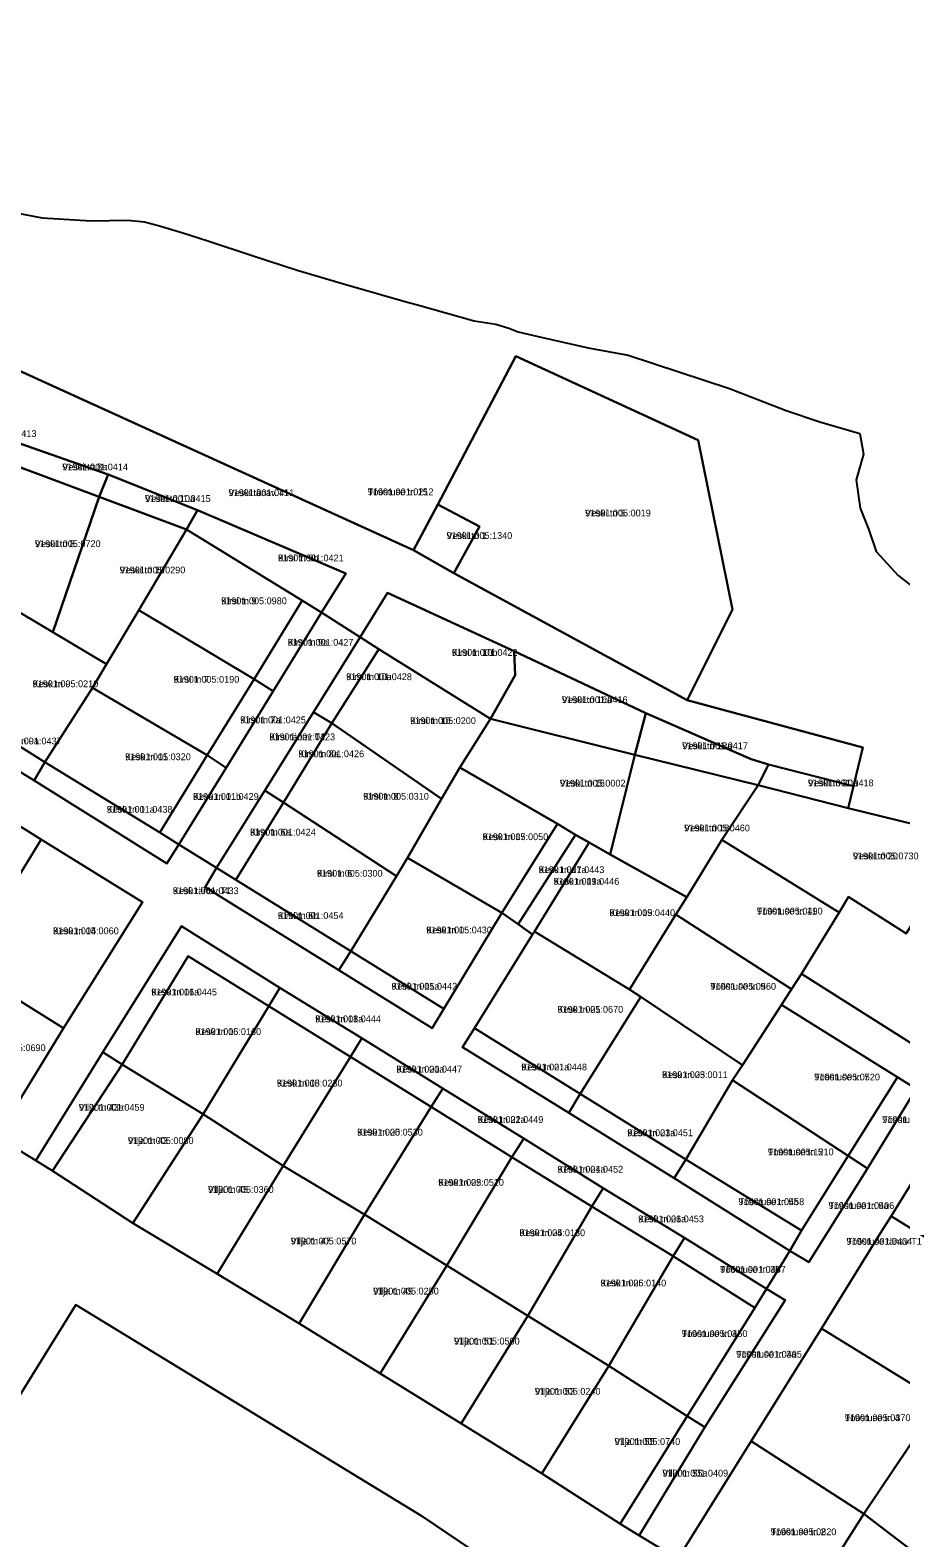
# Model space of a CAD drawing. Extents: x 675810 to 681273, y 6411190 to 6417565.
# Drawn here: x 679020.6 to 679212.9, y 6415637.7 to 6415970.5 of the extents above; entities that cross this region are included whole.
import ezdxf

# ---------------------------------------------------------------- set-up
doc = ezdxf.new("R2010")
doc.units = 0
for name, color, linetype in [('L_AADRESS', 7, 'Continuous'), ('PIIR', 7, 'Continuous'), ('TUNNUS', 7, 'Continuous')]:
    doc.layers.add(name, color=color, linetype=linetype)

msp = doc.modelspace()

# ---------------------------------------------------------------- linework, layer by layer
at = {"layer": 'PIIR'}
for points in [[(679418.32, 6415681.66), (679372.45, 6415703.1), (679376.15, 6415709.11), (679339.93, 6415731.36), (679341.68, 6415734.46), (679247.81, 6415787.97), (679240.52, 6415784.31), (679227.34, 6415792.31), (679201.2, 6415798.72), (679202.38, 6415803.59), (679204.44, 6415812.13), (679165.65, 6415822.55), (679175.65, 6415842.58), (679168.11, 6415879.95), (679127.82, 6415898.47), (679110.64, 6415865.76), (679105.26, 6415855.66), (678938.35, 6415931.63), (678872.23, 6415963.49), (678840.09, 6415967.49), (678816.91, 6415970.45)], [(679012.5, 6415931.11), (679023.26, 6415929.06), (679034.04, 6415928.4), (679042.16, 6415928.54), (679045.83, 6415928.14), (679049.13, 6415927.27), (679054.3, 6415925.72), (679059.82, 6415923.96), (679069.61, 6415920.74), (679079.59, 6415917.48), (679090.33, 6415914.31), (679103.61, 6415910.5), (679106.1, 6415909.8), (679118.61, 6415906.26), (679123.43, 6415905.59), (679126.31, 6415904.7), (679128.36, 6415903.87), (679132.78, 6415902.83), (679143.79, 6415900.33), (679152.61, 6415898.74), (679175.03, 6415891.38), (679187.53, 6415886.48), (679194.97, 6415884), (679203.78, 6415881.45), (679204.58, 6415876.83), (679202.98, 6415871.19), (679203.84, 6415864.94), (679205.8, 6415860.17), (679207.43, 6415855.35), (679212.29, 6415850.08), (679215.84, 6415847.26)], [(678819.79, 6415844.47), (678838.07, 6415834.5), (678867.97, 6415815.62), (678879.6, 6415808.84), (678883.9, 6415806.35), (678901.67, 6415794.69), (678919.6, 6415783.76), (678937.53, 6415772.83), (678955.46, 6415761.9), (678973.27, 6415750.97), (678991.08, 6415739.95), (679013.28, 6415726.22), (679021.83, 6415720.99), (679025.55, 6415718.7), (679043.31, 6415707.12), (679061.88, 6415695.92), (679080, 6415684.98), (679097.88, 6415673.97), (679115.74, 6415662.92), (679133.58, 6415651.86), (679150.85, 6415640.79), (679155.1, 6415638.2), (679163.58, 6415633.02)], [(679002.22, 6415816.67), (679021.5, 6415804.84), (679050.78, 6415786.53), (679053.4, 6415790.68), (679061.78, 6415785.53), (679059.22, 6415781.3), (679088.73, 6415763), (679109.36, 6415750.16), (679111.92, 6415754.42), (679124.73, 6415775.65), (679128.33, 6415773.12), (679131.49, 6415770.86), (679118.72, 6415750.19), (679116.09, 6415745.97), (679139.51, 6415731.51), (679162.79, 6415717.04), (679188.31, 6415701.04), (679183.17, 6415692.68), (679165.05, 6415703.91), (679147.11, 6415714.83), (679129.63, 6415725.8), (679111.7, 6415736.84), (679093.84, 6415747.95), (679075.75, 6415759.1), (679053.99, 6415772.66), (679036.68, 6415744.85), (679021.83, 6415720.99), (679013.28, 6415726.22), (679027.96, 6415750.19), (679045.44, 6415777.97), (679023.06, 6415791.8), (679005.36, 6415802.84)], [(679209.06, 6415573.64), (679107.25, 6415642.36), (679030.7, 6415689.1), (678989.81, 6415623.26)]]:
    msp.add_lwpolyline(points, dxfattribs=at)
for points in [[(678929.48, 6415916.98), (678938.35, 6415931.63), (679105.26, 6415855.66), (679114.18, 6415850.62), (679165.65, 6415822.55), (679204.44, 6415812.13), (679202.38, 6415803.59), (679183.64, 6415808.38), (679179.78, 6415809.54), (679156.58, 6415819.69), (679127.49, 6415833.35), (679099.54, 6415846.24), (679093.45, 6415836.45), (679084.93, 6415841.89), (679090.32, 6415850.54), (679057.56, 6415864.54), (679037.79, 6415872.39), (679018.58, 6415879.14), (678998.13, 6415886.78), (678998.97, 6415889.41), (678974.02, 6415900.22), (678944.77, 6415913.36), (678942.12, 6415909.13)], [(679127.82, 6415898.47), (679168.11, 6415879.95), (679175.65, 6415842.58), (679165.65, 6415822.55), (679114.18, 6415850.62), (679119.84, 6415860.93), (679110.64, 6415865.76)], [(679016.9, 6415874.51), (679018.58, 6415879.14), (679037.79, 6415872.39), (679035.82, 6415867.44)], [(679025.58, 6415837.61), (679018.34, 6415841.95), (679007.49, 6415848.26), (679016.9, 6415874.51), (679035.82, 6415867.44)], [(679035.82, 6415867.44), (679037.79, 6415872.39), (679057.56, 6415864.54), (679055.14, 6415860.24)], [(679025.58, 6415837.61), (679035.82, 6415867.44), (679055.14, 6415860.24), (679044.59, 6415842.43), (679037.46, 6415830.49)], [(679119.84, 6415860.93), (679114.18, 6415850.62), (679105.26, 6415855.66), (679110.64, 6415865.76)], [(679055.14, 6415860.24), (679057.56, 6415864.54), (679090.32, 6415850.54), (679084.93, 6415841.89), (679080.68, 6415844.57)], [(679070.04, 6415827.24), (679044.59, 6415842.43), (679055.14, 6415860.24), (679080.68, 6415844.57)], [(679097.6, 6415833.8), (679093.45, 6415836.45), (679099.54, 6415846.24), (679127.49, 6415833.35), (679127.73, 6415828.09), (679122.23, 6415818.46)], [(679059.7, 6415810.41), (679034.34, 6415825.26), (679037.46, 6415830.49), (679044.59, 6415842.43), (679070.04, 6415827.24)], [(679074.26, 6415824.58), (679070.04, 6415827.24), (679080.68, 6415844.57), (679084.93, 6415841.89)], [(679025.58, 6415837.61), (679037.46, 6415830.49), (679034.34, 6415825.26), (679023.84, 6415808.91), (679004.82, 6415820.78), (679018.34, 6415841.95)], [(679061.78, 6415785.53), (679053.4, 6415790.68), (679063.89, 6415807.64), (679074.26, 6415824.58), (679084.93, 6415841.89), (679093.45, 6415836.45), (679083.18, 6415819.94), (679072.44, 6415802.64)], [(679087.24, 6415817.5), (679083.18, 6415819.94), (679093.45, 6415836.45), (679097.6, 6415833.8)], [(679097.6, 6415833.8), (679122.23, 6415818.46), (679115.45, 6415807.71), (679111.45, 6415800.77), (679087.24, 6415817.5)], [(679127.73, 6415828.09), (679127.49, 6415833.35), (679156.58, 6415819.69), (679154.08, 6415810.49), (679122.23, 6415818.46)], [(679063.89, 6415807.64), (679059.7, 6415810.41), (679070.04, 6415827.24), (679074.26, 6415824.58)], [(679034.34, 6415825.26), (679059.7, 6415810.41), (679049.25, 6415793.38), (679023.84, 6415808.91)], [(679002.22, 6415816.67), (679004.82, 6415820.78), (679023.84, 6415808.91), (679021.5, 6415804.84)], [(679076.54, 6415800.01), (679072.44, 6415802.64), (679083.18, 6415819.94), (679087.24, 6415817.5)], [(679154.08, 6415810.49), (679156.58, 6415819.69), (679179.78, 6415809.54), (679183.64, 6415808.38), (679181.33, 6415803.8)], [(679087.24, 6415817.5), (679111.45, 6415800.77), (679103.93, 6415787.8), (679101.47, 6415783.7), (679076.54, 6415800.01)], [(679137.06, 6415795.24), (679115.45, 6415807.71), (679122.23, 6415818.46), (679154.08, 6415810.49), (679148.7, 6415788.53), (679144.04, 6415791.13), (679141.04, 6415792.83)], [(679053.4, 6415790.68), (679049.25, 6415793.38), (679059.7, 6415810.41), (679063.89, 6415807.64)], [(679173.32, 6415791.71), (679165.58, 6415779.09), (679148.7, 6415788.53), (679154.08, 6415810.49), (679181.33, 6415803.8)], [(679021.5, 6415804.84), (679023.84, 6415808.91), (679049.25, 6415793.38), (679053.4, 6415790.68), (679050.78, 6415786.53)], [(679124.73, 6415775.65), (679103.93, 6415787.8), (679111.45, 6415800.77), (679115.45, 6415807.71), (679137.06, 6415795.24)], [(679181.33, 6415803.8), (679183.64, 6415808.38), (679202.38, 6415803.59), (679201.2, 6415798.72)], [(678988.02, 6415774.82), (679002.54, 6415798.78), (679005.36, 6415802.84), (679023.06, 6415791.8), (679005.89, 6415763.94)], [(679066.04, 6415782.94), (679061.78, 6415785.53), (679072.44, 6415802.64), (679076.54, 6415800.01)], [(679227.34, 6415792.31), (679214.01, 6415771.08), (679201.32, 6415779.15), (679199.24, 6415775.74), (679173.32, 6415791.71), (679181.33, 6415803.8), (679201.2, 6415798.72)], [(679076.54, 6415800.01), (679101.47, 6415783.7), (679091.4, 6415767.19), (679066.04, 6415782.94)], [(679128.33, 6415773.12), (679124.73, 6415775.65), (679137.06, 6415795.24), (679141.04, 6415792.83)], [(679128.33, 6415773.12), (679141.04, 6415792.83), (679144.04, 6415791.13), (679131.96, 6415771.5), (679131.49, 6415770.86)], [(679023.06, 6415791.8), (679045.44, 6415777.97), (679027.96, 6415750.19), (679005.89, 6415763.94)], [(679163.17, 6415775.29), (679152.92, 6415758.7), (679131.96, 6415771.5), (679144.04, 6415791.13), (679148.7, 6415788.53), (679165.58, 6415779.09)], [(679163.17, 6415775.29), (679165.58, 6415779.09), (679173.32, 6415791.71), (679199.24, 6415775.74), (679190.94, 6415762.16), (679188.68, 6415758.8)], [(679240.52, 6415784.31), (679234.07, 6415774.13), (679216.42, 6415746.08), (679190.94, 6415762.16), (679199.24, 6415775.74), (679201.32, 6415779.15), (679214.01, 6415771.08), (679227.34, 6415792.31)], [(679101.47, 6415783.7), (679103.93, 6415787.8), (679124.73, 6415775.65), (679111.92, 6415754.42), (679091.4, 6415767.19)], [(679059.22, 6415781.3), (679061.78, 6415785.53), (679066.04, 6415782.94), (679091.4, 6415767.19), (679088.73, 6415763)], [(679040.9, 6415742.15), (679036.68, 6415744.85), (679053.99, 6415772.66), (679075.75, 6415759.1), (679073.28, 6415755.01), (679055.47, 6415766.07)], [(679155.46, 6415757.09), (679152.92, 6415758.7), (679163.17, 6415775.29), (679188.68, 6415758.8), (679186.52, 6415755.32), (679177.89, 6415742.04)], [(679131.96, 6415771.5), (679152.92, 6415758.7), (679155.46, 6415757.09), (679142.08, 6415735.65), (679118.72, 6415750.19), (679131.49, 6415770.86)], [(679163.58, 6415633.02), (679155.1, 6415638.2), (679169.58, 6415662.1), (679187.29, 6415690.12), (679183.17, 6415692.68), (679188.31, 6415701.04), (679192.5, 6415698.51), (679205.47, 6415719.21), (679216.26, 6415736.76), (679212.15, 6415739.39), (679186.52, 6415755.32), (679188.68, 6415758.8), (679190.94, 6415762.16), (679216.42, 6415746.08), (679220.47, 6415743.64), (679237.97, 6415771.73), (679246.64, 6415766.45), (679226.57, 6415734.31), (679210.69, 6415708.71), (679208.62, 6415705.42), (679195.3, 6415683.87), (679179.77, 6415659.03)], [(679040.9, 6415742.15), (679055.47, 6415766.07), (679073.28, 6415755.01), (679058.83, 6415731.21)], [(679088.73, 6415763), (679091.4, 6415767.19), (679111.92, 6415754.42), (679109.36, 6415750.16)], [(679005.89, 6415763.94), (679027.96, 6415750.19), (679013.28, 6415726.22), (678991.08, 6415739.95)], [(679073.28, 6415755.01), (679075.75, 6415759.1), (679093.84, 6415747.95), (679091.31, 6415743.86)], [(679142.08, 6415735.65), (679155.46, 6415757.09), (679177.89, 6415742.04), (679175.71, 6415738.7), (679165.37, 6415721.21)], [(679058.83, 6415731.21), (679073.28, 6415755.01), (679091.31, 6415743.86), (679076.44, 6415719.81)], [(679175.71, 6415738.7), (679177.89, 6415742.04), (679186.52, 6415755.32), (679212.15, 6415739.39), (679201.22, 6415721.97)], [(679116.09, 6415745.97), (679118.72, 6415750.19), (679142.08, 6415735.65), (679139.51, 6415731.51)], [(679091.31, 6415743.86), (679093.84, 6415747.95), (679111.7, 6415736.84), (679109.13, 6415732.8)], [(679025.55, 6415718.7), (679021.83, 6415720.99), (679036.68, 6415744.85), (679040.9, 6415742.15)], [(679094.42, 6415709.02), (679076.44, 6415719.81), (679091.31, 6415743.86), (679109.13, 6415732.8)], [(679043.31, 6415707.12), (679025.55, 6415718.7), (679040.9, 6415742.15), (679058.83, 6415731.21)], [(679205.47, 6415719.21), (679201.22, 6415721.97), (679212.15, 6415739.39), (679216.26, 6415736.76)], [(679109.13, 6415732.8), (679111.7, 6415736.84), (679129.63, 6415725.8), (679126.99, 6415721.69)], [(679190.95, 6415705.51), (679165.37, 6415721.21), (679175.71, 6415738.7), (679201.24, 6415722.02)], [(679112.63, 6415697.78), (679094.42, 6415709.02), (679109.13, 6415732.8), (679126.99, 6415721.69)], [(679139.51, 6415731.51), (679142.08, 6415735.65), (679165.37, 6415721.21), (679162.79, 6415717.04)], [(679210.69, 6415708.71), (679226.57, 6415734.31), (679253.82, 6415718.26), (679248.54, 6415710.1), (679237.06, 6415692.46)], [(679043.31, 6415707.12), (679058.83, 6415731.21), (679076.44, 6415719.81), (679061.88, 6415695.92)], [(679126.99, 6415721.69), (679129.63, 6415725.8), (679147.11, 6415714.83), (679144.63, 6415710.79)], [(679076.44, 6415719.81), (679094.42, 6415709.02), (679080, 6415684.98), (679061.88, 6415695.92)], [(679112.63, 6415697.78), (679126.99, 6415721.69), (679144.63, 6415710.79), (679130.5, 6415686.71)], [(679162.79, 6415717.04), (679165.37, 6415721.21), (679190.95, 6415705.51), (679188.31, 6415701.04)], [(679192.5, 6415698.51), (679188.31, 6415701.04), (679190.95, 6415705.51), (679201.22, 6415721.97), (679205.47, 6415719.21)], [(679144.63, 6415710.79), (679147.11, 6415714.83), (679165.05, 6415703.91), (679162.61, 6415699.84)], [(679130.5, 6415686.71), (679144.63, 6415710.79), (679162.61, 6415699.84), (679148.34, 6415675.64)], [(679237.06, 6415692.46), (679248.54, 6415710.1), (679277.39, 6415691.1), (679306.26, 6415672.05), (679335.12, 6415653.05), (679316.48, 6415618.21), (679301.31, 6415612.53), (679223.54, 6415583.42), (679222.37, 6415587.28), (679259.47, 6415601.16), (679204.65, 6415643.01), (679221.39, 6415667.86)], [(679080, 6415684.98), (679094.42, 6415709.02), (679112.63, 6415697.78), (679097.88, 6415673.97)], [(679237.06, 6415692.46), (679221.39, 6415667.86), (679195.3, 6415683.87), (679208.62, 6415705.42), (679210.69, 6415708.71)], [(679162.61, 6415699.84), (679165.05, 6415703.91), (679183.17, 6415692.68), (679180.61, 6415688.47)], [(679180.61, 6415688.47), (679165.7, 6415664.57), (679148.34, 6415675.64), (679162.61, 6415699.84)], [(679097.88, 6415673.97), (679112.63, 6415697.78), (679130.5, 6415686.71), (679115.74, 6415662.92)], [(679169.58, 6415662.1), (679165.7, 6415664.57), (679180.61, 6415688.47), (679183.17, 6415692.68), (679187.29, 6415690.12)], [(679107.25, 6415642.36), (679209.06, 6415573.64), (679235.94, 6415523.12), (679269.34, 6415417.57), (679263.6, 6415410.66), (679213.57, 6415387.53), (679202.07, 6415417.43), (679144.86, 6415396.49), (679135.51, 6415422.06), (679089.93, 6415556), (679070.56, 6415610.67), (679030.28, 6415597.11), (678989.81, 6415623.26), (679030.7, 6415689.1)], [(679115.74, 6415662.92), (679130.5, 6415686.71), (679148.34, 6415675.64), (679133.58, 6415651.86)], [(679195.3, 6415683.87), (679221.39, 6415667.86), (679204.65, 6415643.01), (679179.77, 6415659.03)], [(679133.58, 6415651.86), (679148.34, 6415675.64), (679165.7, 6415664.57), (679150.85, 6415640.79)], [(679155.1, 6415638.2), (679150.85, 6415640.79), (679165.7, 6415664.57), (679169.58, 6415662.1)], [(679204.65, 6415643.01), (679188.58, 6415617.54), (679163.58, 6415633.02), (679179.77, 6415659.03)], [(679188.58, 6415617.54), (679204.65, 6415643.01), (679259.47, 6415601.16), (679222.37, 6415587.28), (679221.77, 6415588.98), (679208.41, 6415599.7), (679186.54, 6415614.19)]]:
    msp.add_lwpolyline(points, close=True, dxfattribs=at)

# ---------------------------------------------------------------- texts
at = {"layer": 'L_AADRESS'}
for s, p in [('Veski tn 8a', (679027.7, 6415873.29)), ('Veski tänav T1', (679064.42, 6415867.61)), ('Tööstuse tn 15', (679095.15, 6415867.8)), ('Veski tn 10a', (679045.96, 6415866.32)), ('Veski tn 3', (679143.14, 6415863.12)), ('Veski tn 1', (679112.55, 6415858.15)), ('Veski tn 8', (679021.66, 6415856.35)), ('Kirsi tn 9b', (679075.33, 6415853.21)), ('Veski tn 10', (679040.36, 6415850.55)), ('Kirsi tn 9', (679062.77, 6415843.74)), ('Kirsi tn 9a', (679077.48, 6415834.59)), ('Kirsi tn 10b', (679113.73, 6415832.35)), ('Kesk tn 9', (679021.14, 6415825.43)), ('Kirsi tn 7', (679052.28, 6415826.42)), ('Kirsi tn 10a', (679090.39, 6415826.99)), ('Veski tn 16a', (679138.02, 6415821.92)), ('Kirsi tn 7a', (679066.98, 6415817.47)), ('Kirsi tn 10', (679104.52, 6415817.29)), ('Kesk tn 9a', (679013.05, 6415812.81)), ('Kirsi tänav T1', (679073.43, 6415813.72)), ('Veski tn 18a', (679164.58, 6415811.75)), ('Kesk tn 11', (679041.57, 6415809.32)), ('Kirsi tn 8a', (679079.84, 6415809.98)), ('Veski tn 16', (679137.56, 6415803.5)), ('Veski tn 20a', (679192.34, 6415803.55)), ('Kesk tn 11a', (679037.52, 6415797.72)), ('Kesk tn 11b', (679056.57, 6415800.56)), ('Kirsi tn 8', (679094.13, 6415800.6)), ('Kirsi tn 6a', (679069.16, 6415792.69)), ('Kesk tn 17', (679120.5, 6415791.68)), ('Veski tn 18', (679165.02, 6415793.61)), ('Kesk tn 17a', (679132.88, 6415784.4)), ('Veski tn 20', (679202.27, 6415787.44)), ('Kirsi tn 6', (679083.93, 6415783.6)), ('Kesk tn 19a', (679136.18, 6415781.83)), ('Kesk tänav T1', (679052.12, 6415779.76)), ('Kirsi tn 6b', (679075.29, 6415774.27)), ('Kesk tn 19', (679148.5, 6415774.91)), ('Tööstuse tn 11', (679181.08, 6415775.26)), ('Kesk tn 14', (679025.66, 6415770.91)), ('Kesk tn 15', (679108.06, 6415771.1)), ('Kesk tn 15a', (679100.38, 6415758.68)), ('Tööstuse tn 9', (679170.79, 6415758.66)), ('Kesk tn 16a', (679047.34, 6415757.4)), ('Kesk tn 18a', (679083.55, 6415751.48)), ('Kesk tn 21', (679137.04, 6415753.57)), ('Kesk tn 16', (679057.09, 6415748.67)), ('Kesk tn 20a', (679101.47, 6415740.38)), ('Kesk tn 21a', (679129.05, 6415740.85)), ('Kesk tn 23', (679160.13, 6415739.15)), ('Tööstuse tn 7', (679193.74, 6415738.65)), ('Kesk tn 18', (679075.07, 6415737.3)), ('Vilja tn 43a', (679031.36, 6415731.95)), ('Kesk tn 22a', (679119.41, 6415729.27)), ('Tööstuse tn 7a', (679208.74, 6415729.24)), ('Vilja tn 43', (679042.19, 6415724.61)), ('Kesk tn 20', (679092.79, 6415726.47)), ('Kesk tn 23a', (679152.45, 6415726.34)), ('Tööstuse tn 5', (679183.5, 6415722.11)), ('Kesk tn 24a', (679137.04, 6415718.29)), ('Kesk tn 22', (679110.71, 6415715.39)), ('Vilja tn 45', (679059.88, 6415713.83)), ('Tööstuse tn 5b', (679177.01, 6415711.12)), ('Tööstuse tn 5a', (679196.89, 6415710.27)), ('Kesk tn 26a', (679154.86, 6415707.33)), ('Vilja tn 47', (679078.15, 6415702.44)), ('Kesk tn 24', (679128.63, 6415704.27)), ('Tööstuse tänav T1', (679200.87, 6415702.37)), ('Tööstuse tn 3b', (679172.95, 6415696.19)), ('Vilja tn 49', (679096.32, 6415691.39)), ('Kesk tn 26', (679146.55, 6415693.18)), ('Tööstuse tn 3', (679164.48, 6415682.01)), ('Vilja tn 51', (679114.19, 6415680.35)), ('Tööstuse tn 3a', (679176.5, 6415677.46)), ('Vilja tn 53', (679132.04, 6415669.28)), ('Tööstuse tn 4', (679200.47, 6415663.44)), ('Vilja tn 55', (679149.64, 6415658.19)), ('Vilja tn 55a', (679160.21, 6415651.21)), ('Tööstuse tn 2', (679184.11, 6415638.27))]:
    msp.add_text(s, height=1.5, dxfattribs=at).set_placement(p)
at = {"layer": 'TUNNUS'}
for s, p in [('91901:001:0413', (679007.49, 6415880.65)), ('91901:001:0414', (679027.7, 6415873.29)), ('91901:001:0411', (679064.42, 6415867.61)), ('91901:001:0212', (679095.15, 6415867.8)), ('91901:001:0415', (679045.96, 6415866.32)), ('91901:005:0019', (679143.14, 6415863.12)), ('91901:005:1340', (679112.55, 6415858.15)), ('91901:005:0720', (679021.66, 6415856.35)), ('91901:001:0421', (679075.33, 6415853.21)), ('91901:005:0290', (679040.36, 6415850.55)), ('91901:005:0980', (679062.77, 6415843.74)), ('91901:001:0427', (679077.48, 6415834.59)), ('91901:001:0422', (679113.73, 6415832.35)), ('91901:005:0210', (679021.14, 6415825.43)), ('91901:005:0190', (679052.28, 6415826.42)), ('91901:001:0428', (679090.39, 6415826.99)), ('91901:001:0416', (679138.02, 6415821.92)), ('91901:001:0425', (679066.98, 6415817.47)), ('91901:005:0200', (679104.52, 6415817.29)), ('91901:001:0437', (679013.05, 6415812.81)), ('91901:001:0423', (679073.43, 6415813.72)), ('91901:001:0417', (679164.58, 6415811.75)), ('91901:005:0320', (679041.57, 6415809.32)), ('91901:001:0426', (679079.84, 6415809.98)), ('91901:005:0002', (679137.56, 6415803.5)), ('91901:001:0418', (679192.34, 6415803.55)), ('91901:001:0438', (679037.52, 6415797.72)), ('91901:001:0429', (679056.57, 6415800.56)), ('91901:005:0310', (679094.13, 6415800.6)), ('91901:001:0424', (679069.16, 6415792.69)), ('91901:005:0050', (679120.5, 6415791.68)), ('91901:005:0460', (679165.02, 6415793.61)), ('91901:001:0443', (679132.88, 6415784.4)), ('91901:005:0730', (679202.27, 6415787.44)), ('91901:005:0300', (679083.93, 6415783.6)), ('91901:001:0446', (679136.18, 6415781.83)), ('91901:001:0433', (679052.12, 6415779.76)), ('91901:001:0454', (679075.29, 6415774.27)), ('91901:005:0440', (679148.5, 6415774.91)), ('91901:005:0490', (679181.08, 6415775.26)), ('91901:005:0060', (679025.66, 6415770.91)), ('91901:005:0430', (679108.06, 6415771.1)), ('91901:001:0442', (679100.38, 6415758.68)), ('91901:005:0560', (679170.79, 6415758.66)), ('91901:001:0445', (679047.34, 6415757.4)), ('91901:001:0444', (679083.55, 6415751.48)), ('91901:005:0670', (679137.04, 6415753.57)), ('91901:005:0160', (679057.09, 6415748.67)), ('91901:005:0690', (679009.52, 6415745.11)), ('91901:001:0447', (679101.47, 6415740.38)), ('91901:001:0448', (679129.05, 6415740.85)), ('91901:005:0011', (679160.13, 6415739.15)), ('91901:005:0520', (679193.74, 6415738.65)), ('91901:005:0230', (679075.07, 6415737.3)), ('91901:001:0459', (679031.36, 6415731.95)), ('91901:001:0449', (679119.41, 6415729.27)), ('91901:001:0407', (679208.74, 6415729.24)), ('91901:005:0080', (679042.19, 6415724.61)), ('91901:005:0530', (679092.79, 6415726.47)), ('91901:001:0451', (679152.45, 6415726.34)), ('91901:005:1210', (679183.5, 6415722.11)), ('91901:001:0452', (679137.04, 6415718.29)), ('91901:005:0510', (679110.71, 6415715.39)), ('91901:005:0360', (679059.88, 6415713.83)), ('91901:001:0458', (679177.01, 6415711.12)), ('91901:001:0406', (679196.89, 6415710.27)), ('91901:001:0453', (679154.86, 6415707.33)), ('91901:005:0570', (679078.15, 6415702.44)), ('91901:005:0130', (679128.63, 6415704.27)), ('91901:001:0404', (679200.87, 6415702.37)), ('91901:001:0457', (679172.95, 6415696.19)), ('91901:005:0250', (679096.32, 6415691.39)), ('91901:005:0140', (679146.55, 6415693.18)), ('91901:005:0450', (679164.48, 6415682.01)), ('91901:005:0500', (679114.19, 6415680.35)), ('91901:001:0405', (679176.5, 6415677.46)), ('91901:005:0240', (679132.04, 6415669.28)), ('91901:005:0370', (679200.47, 6415663.44)), ('91901:005:0740', (679149.64, 6415658.19)), ('91901:001:0409', (679160.21, 6415651.21)), ('91901:005:0820', (679184.11, 6415638.27))]:
    msp.add_text(s, height=1.5, dxfattribs=at).set_placement(p)

doc.saveas('drawing.dxf')
